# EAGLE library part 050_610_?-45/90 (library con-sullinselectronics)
.050 DIP EDGE CARD CONNECTOR .050 [1.27mm] CONTACT CENTERS .610" INSULATEOR HEIGHT Source: .050 DIP EDGE CARD.pdf
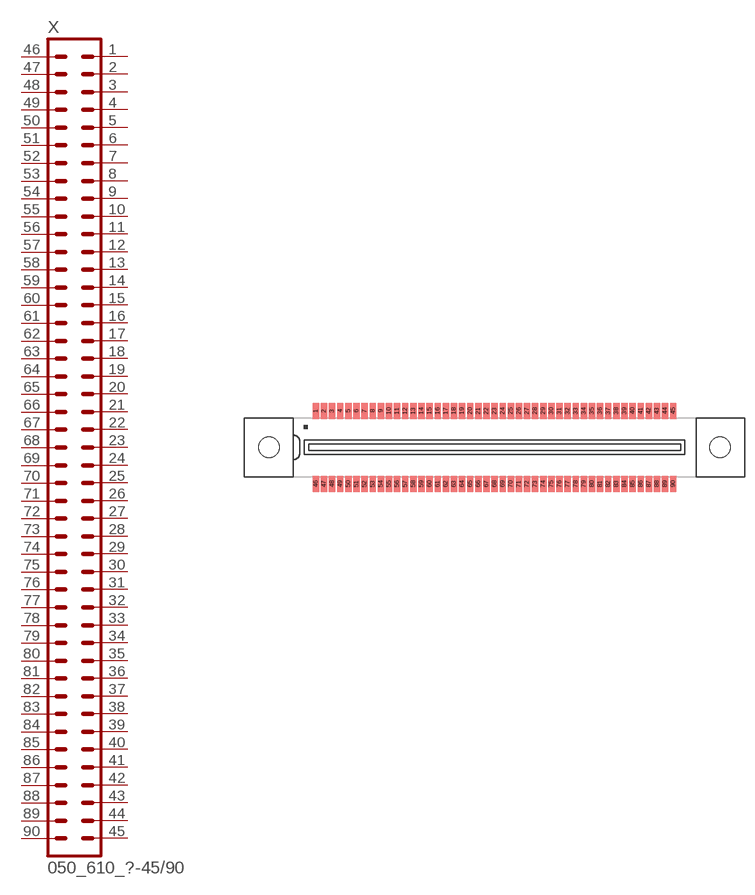
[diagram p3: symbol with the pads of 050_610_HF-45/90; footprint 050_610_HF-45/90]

Designator prefix X

## 050_610_HF-45/90 (OC_FARNELL: unknown; OC_NEWARK: unknown)  [050_610_HF-45/90]
1  1  pas
2  2  pas
3  3  pas
4  4  pas
5  5  pas
6  6  pas
7  7  pas
8  8  pas
9  9  pas
10  10  pas
11  11  pas
12  12  pas
13  13  pas
14  14  pas
15  15  pas
16  16  pas
17  17  pas
18  18  pas
19  19  pas
20  20  pas
21  21  pas
22  22  pas
23  23  pas
24  24  pas
25  25  pas
26  26  pas
27  27  pas
28  28  pas
29  29  pas
30  30  pas
31  31  pas
32  32  pas
33  33  pas
34  34  pas
35  35  pas
36  36  pas
37  37  pas
38  38  pas
39  39  pas
40  40  pas
41  41  pas
42  42  pas
43  43  pas
44  44  pas
45  45  pas
46  46  pas
47  47  pas
48  48  pas
49  49  pas
50  50  pas
51  51  pas
52  52  pas
53  53  pas
54  54  pas
55  55  pas
56  56  pas
57  57  pas
58  58  pas
59  59  pas
60  60  pas
61  61  pas
62  62  pas
63  63  pas
64  64  pas
65  65  pas
66  66  pas
67  67  pas
68  68  pas
69  69  pas
70  70  pas
71  71  pas
72  72  pas
73  73  pas
74  74  pas
75  75  pas
76  76  pas
77  77  pas
78  78  pas
79  79  pas
80  80  pas
81  81  pas
82  82  pas
83  83  pas
84  84  pas
85  85  pas
86  86  pas
87  87  pas
88  88  pas
89  89  pas
90  90  pas

## Footprint 050_610_HF-45/90 (pad centres in mm)
.050 DIP EDGE CARD CONNECTOR SURFACE MOUNT .050 [1.27mm] CONTACT CENTERS .610" INSULATEOR HEIGHT Source: .050 DIP EDGE CARD.pdf
smd 1 x 2.5: 1 -27.94,5.715; 2 -26.67,5.715; 3 -25.4,5.715; 4 -24.13,5.715; 5 -22.86,5.715; 6 -21.59,5.715; 7 -20.32,5.715; 8 -19.05,5.715; 9 -17.78,5.715; 10 -16.51,5.715; 11 -15.24,5.715; 12 -13.97,5.715; 13 -12.7,5.715; 14 -11.43,5.715; 15 -10.16,5.715; 16 -8.89,5.715; 17 -7.62,5.715; 18 -6.35,5.715; 19 -5.08,5.715; 20 -3.81,5.715; 21 -2.54,5.715; 22 -1.27,5.715; 23 0,5.715; 24 1.27,5.715; 25 2.54,5.715; 26 3.81,5.715; 27 5.08,5.715; 28 6.35,5.715; 29 7.62,5.715; 30 8.89,5.715; 31 10.16,5.715; 32 11.43,5.715; 33 12.7,5.715; 34 13.97,5.715; 35 15.24,5.715; 36 16.51,5.715; 37 17.78,5.715; 38 19.05,5.715; 39 20.32,5.715; 40 21.59,5.715; 41 22.86,5.715; 42 24.13,5.715; 43 25.4,5.715; 44 26.67,5.715; 45 27.94,5.715; 46 -27.94,-5.715; 47 -26.67,-5.715; 48 -25.4,-5.715; 49 -24.13,-5.715; 50 -22.86,-5.715; 51 -21.59,-5.715; 52 -20.32,-5.715; 53 -19.05,-5.715; 54 -17.78,-5.715; 55 -16.51,-5.715; 56 -15.24,-5.715; 57 -13.97,-5.715; 58 -12.7,-5.715; 59 -11.43,-5.715; 60 -10.16,-5.715; 61 -8.89,-5.715; 62 -7.62,-5.715; 63 -6.35,-5.715; 64 -5.08,-5.715; 65 -3.81,-5.715; 66 -2.54,-5.715; 67 -1.27,-5.715; 68 0,-5.715; 69 1.27,-5.715; 70 2.54,-5.715; 71 3.81,-5.715; 72 5.08,-5.715; 73 6.35,-5.715; 74 7.62,-5.715; 75 8.89,-5.715; 76 10.16,-5.715; 77 11.43,-5.715; 78 12.7,-5.715; 79 13.97,-5.715; 80 15.24,-5.715; 81 16.51,-5.715; 82 17.78,-5.715; 83 19.05,-5.715; 84 20.32,-5.715; 85 21.59,-5.715; 86 22.86,-5.715; 87 24.13,-5.715; 88 25.4,-5.715; 89 26.67,-5.715; 90 27.94,-5.715
hole 3.18 at -35.255,0
hole 3.18 at 35.255,0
